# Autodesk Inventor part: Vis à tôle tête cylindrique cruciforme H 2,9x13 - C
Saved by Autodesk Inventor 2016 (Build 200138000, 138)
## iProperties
Created: 2003-09
Part Number: Vis à tôle tête cylindrique cruciforme H 2,9x13 - C
Material: Générique
Document SubType Name: Modeling
Designer: Bruno
Density: 1 g/cm^3
Appearance: Par défaut
Author: Bruno
Sending System: SolidWorks 2013
Last Author: christophe
Last Saved: 2014-02-15
SwCadDb Education & Formation: v2
Swc_Composant: Vis à tête cylindrique cruciforme H (Philips)
Diamètre nominal: 2,9
Longueur sous tête: 13
Diamètre extérieur: 2,9
Diamètre noyau: 2,18
Pas du filetage: 1
Swc_Designation: Vis à tôle tête cylindrique cruciforme H 2,9x13 - C
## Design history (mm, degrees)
feature "Boss.-Balayage7"
node "Solide1"
